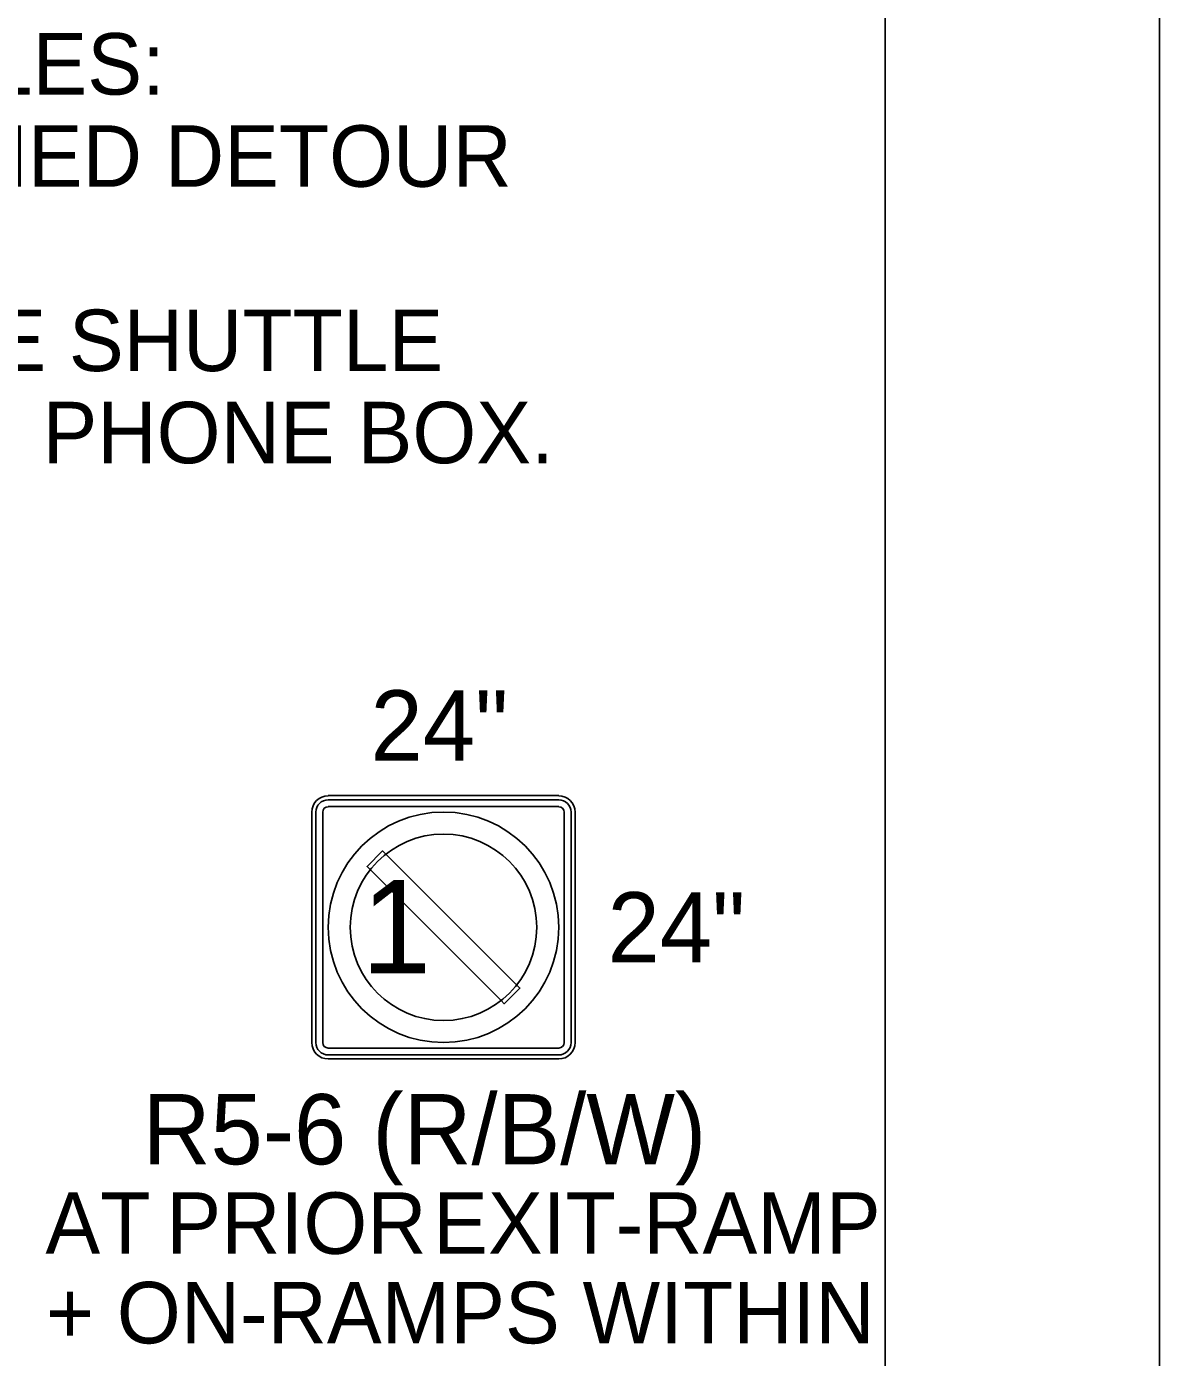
# Model space of a CAD drawing. Extents: x 99999 to 100116, y 99995 to 100013.
# Drawn here: x 100014.772 to 100016.062, y 100001.262 to 100002.778 of the extents above; entities that cross this region are included whole.
import ezdxf

# ---------------------------------------------------------------- set-up
doc = ezdxf.new("R2010")
doc.units = 0
for name, color, linetype in [('SH_GI_GeneralNotesBodyText', 7, 'Continuous'), ('SH_GI_PlotLimits', 7, 'Continuous'), ('SH_GI_SheetBorder', 7, 'Continuous'), ('TR_SN_ConstructionSigns', 7, 'Continuous')]:
    doc.layers.add(name, color=color, linetype=linetype)

msp = doc.modelspace()

# ---------------------------------------------------------------- linework, layer by layer
at = {"layer": 'SH_GI_PlotLimits'}
msp.add_lwpolyline([(99999.0625, 99999.6875), (100016.0625, 99999.6875), (100016.0625, 100010.6875), (99999.0625, 100010.6875)], close=True, dxfattribs=at)
at = {"layer": 'SH_GI_SheetBorder'}
msp.add_line((100015.75, 100010.375), (100015.75, 100000), dxfattribs=at)
at = {"layer": 'TR_SN_ConstructionSigns'}
for p, q in [((100015.3783, 100001.9019), (100015.1158, 100001.9019)), ((100015.1158, 100001.9019), (100015.3783, 100001.9019)), ((100015.3783, 100001.9019), (100015.1158, 100001.9019)), ((100015.3783, 100001.8972), (100015.1158, 100001.8972)), ((100015.0971, 100001.8831), (100015.0971, 100001.6206)), ((100015.0971, 100001.6206), (100015.0971, 100001.8831)), ((100015.0971, 100001.8831), (100015.0971, 100001.6206)), ((100015.1018, 100001.8831), (100015.1018, 100001.6206)), ((100015.1096, 100001.6206), (100015.1096, 100001.8831)), ((100015.1158, 100001.8894), (100015.3783, 100001.8894)), ((100015.3846, 100001.8831), (100015.3846, 100001.6206)), ((100015.3924, 100001.6206), (100015.3924, 100001.8831)), ((100015.3971, 100001.6206), (100015.3971, 100001.8831)), ((100015.3971, 100001.8831), (100015.3971, 100001.6206)), ((100015.3971, 100001.6206), (100015.3971, 100001.8831)), ((100015.3783, 100001.6144), (100015.1158, 100001.6144)), ((100015.1158, 100001.6066), (100015.3783, 100001.6066)), ((100015.1158, 100001.6019), (100015.3783, 100001.6019)), ((100015.3783, 100001.6019), (100015.1158, 100001.6019)), ((100015.1158, 100001.6019), (100015.3783, 100001.6019))]:
    msp.add_line(p, q, dxfattribs=at)
msp.add_lwpolyline([(100015.3305, 100001.6861), (100015.1813, 100001.8353), (100015.1778, 100001.8389), (100015.1601, 100001.8212), (100015.3128, 100001.6685), (100015.3164, 100001.6649), (100015.3341, 100001.6826), (100015.3305, 100001.6861)], dxfattribs=at)
for radius in [0.1313, 0.1062]:
    msp.add_circle((100015.2471, 100001.7519), radius, dxfattribs=at)
for centre, radius, start, end in [((100015.1158, 100001.8831), 0.0187, 90, 180), ((100015.1158, 100001.8831), 0.0187, 90, 180), ((100015.1158, 100001.8831), 0.0187, 90, 180), ((100015.1158, 100001.8831), 0.0141, 90, 180), ((100015.3783, 100001.8831), 0.0187, 0, 90), ((100015.3783, 100001.8831), 0.0187, 0, 90), ((100015.3783, 100001.8831), 0.0187, 0, 90), ((100015.3783, 100001.8831), 0.0141, 0, 90), ((100015.1158, 100001.8831), 0.00625, 90, 180), ((100015.3783, 100001.8831), 0.00625, 0, 90), ((100015.1158, 100001.6206), 0.0187, 180, 270), ((100015.1158, 100001.6206), 0.0187, 180, 270), ((100015.1158, 100001.6206), 0.0187, 180, 270), ((100015.1158, 100001.6206), 0.0141, 180, 270), ((100015.1158, 100001.6206), 0.00625, 180, 270), ((100015.3783, 100001.6206), 0.0141, 270, 0), ((100015.3783, 100001.6206), 0.00625, 270, 0), ((100015.3783, 100001.6206), 0.0187, 270, 0), ((100015.3783, 100001.6206), 0.0187, 270, 0), ((100015.3783, 100001.6206), 0.0187, 270, 0)]:
    msp.add_arc(centre, radius, start, end, dxfattribs=at)

# ---------------------------------------------------------------- texts
at = {"layer": 'SH_GI_GeneralNotesBodyText'}
for s, p in [('16. BICYCLIST ACCOMMODATIONS, WHERE FACILITY OPEN TO BICYCLES:', (100011.549, 100002.7006)), ('(A) BICYCLES PROHIBITED VIA R5-601 & R5-6 SIGNS. PROVIDE SIGNED DETOUR ', (100011.689, 100002.5956)), ('(B) BICYCLES PROHIBITED VIA R5-601 & R5-6 SIGNS. PROVIDE FREE SHUTTLE ', (100011.689, 100002.3856)), ('(WORK TRUCK, VAN, OR BUS OK) + CONTACT INFORMATION OR PHONE BOX.', (100011.839, 100002.2806))]:
    msp.add_text(s, height=0.07, rotation=360, dxfattribs=at).set_placement(p)
at = {"layer": 'TR_SN_ConstructionSigns'}
for s, height, p in [('24"', 0.08, (100015.164, 100001.9419)), ('24"', 0.08, (100015.434, 100001.7119)), ('R5-6 (R/B/W)', 0.08, (100014.9045, 100001.4819)), ('PRIOR', 0.07, (100014.9314, 100001.3799)), ('AT', 0.07, (100014.7937, 100001.3799)), ('EXIT-RAMP', 0.07, (100015.2353, 100001.3799)), ('+ ON-RAMPS WITHIN', 0.07, (100014.7944, 100001.2779))]:
    msp.add_text(s, height=height, rotation=360, dxfattribs=at).set_placement(p)
msp.add_text('1', height=0.1065, dxfattribs=at).set_placement((100015.1538, 100001.6994))

doc.saveas('drawing.dxf')
